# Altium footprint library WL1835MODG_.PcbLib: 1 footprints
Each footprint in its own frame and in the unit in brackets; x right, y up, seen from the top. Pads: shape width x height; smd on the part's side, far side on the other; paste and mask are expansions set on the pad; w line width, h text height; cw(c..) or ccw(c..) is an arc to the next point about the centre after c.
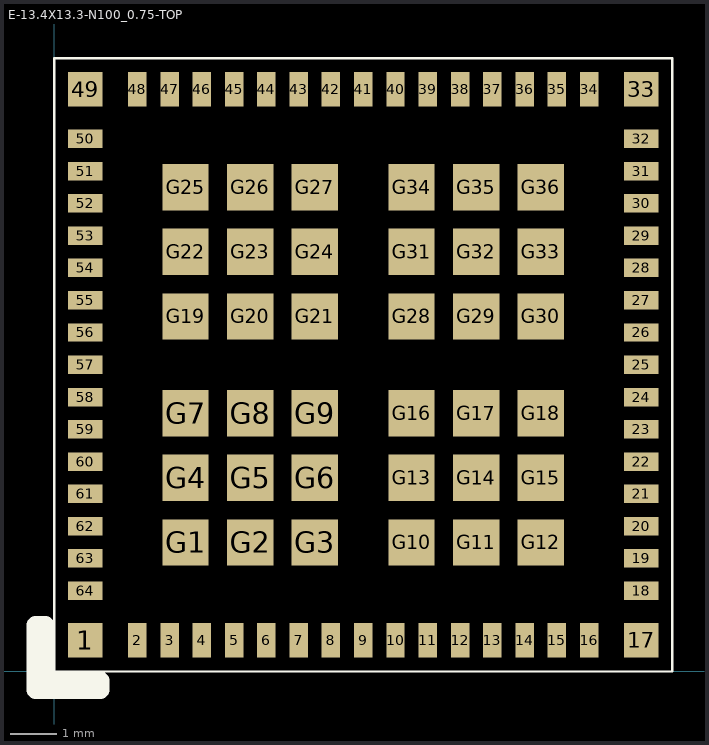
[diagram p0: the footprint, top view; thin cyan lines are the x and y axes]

## E-13.4X13.3-N100_0.75-TOP [mm]
pads (100):
  rect 0.75x0.75 smd mask+0.03: 1(0.675,0.675) 17(12.725,0.675) 33(12.725,12.625) 49(0.675,12.625)
  rect 0.4x0.75 smd mask+0.03: 2(1.8,0.675) 3(2.5,0.675) 4(3.2,0.675) 5(3.9,0.675) 6(4.6,0.675) 7(5.3,0.675) 8(6,0.675) 9(6.7,0.675) 10(7.4,0.675) 11(8.1,0.675) 12(8.8,0.675) 13(9.5,0.675) 14(10.2,0.675) 15(10.9,0.675) 16(11.6,0.675) 34(11.6,12.625) 35(10.9,12.625) 36(10.2,12.625) 37(9.5,12.625) 38(8.8,12.625) 39(8.1,12.625) 40(7.4,12.625) 41(6.7,12.625) 42(6,12.625) 43(5.3,12.625) 44(4.6,12.625) 45(3.9,12.625) 46(3.2,12.625) 47(2.5,12.625) 48(1.8,12.625)
  rect 0.75x0.4 smd mask+0.03: 18(12.725,1.75) 19(12.725,2.45) 20(12.725,3.15) 21(12.725,3.85) 22(12.725,4.55) 23(12.725,5.25) 24(12.725,5.95) 25(12.725,6.65) 26(12.725,7.35) 27(12.725,8.05) 28(12.725,8.75) 29(12.725,9.45) 30(12.725,10.15) 31(12.725,10.85) 32(12.725,11.55) 50(0.675,11.55) 51(0.675,10.85) 52(0.675,10.15) 53(0.675,9.45) 54(0.675,8.75) 55(0.675,8.05) 56(0.675,7.35) 57(0.675,6.65) 58(0.675,5.95) 59(0.675,5.25) 60(0.675,4.55) 61(0.675,3.85) 62(0.675,3.15) 63(0.675,2.45) 64(0.675,1.75)
  rect 1x1 smd mask+0.03: G1(2.85,2.8) G2(4.25,2.8) G3(5.65,2.8) G4(2.85,4.2) G5(4.25,4.2) G6(5.65,4.2) G7(2.85,5.6) G8(4.25,5.6) G9(5.65,5.6) G10(7.75,2.8) G11(9.15,2.8) G12(10.55,2.8) G13(7.75,4.2) G14(9.15,4.2) G15(10.55,4.2) G16(7.75,5.6) G17(9.15,5.6) G18(10.55,5.6) G19(2.85,7.7) G20(4.25,7.7) G21(5.65,7.7) G22(2.85,9.1) G23(4.25,9.1) G24(5.65,9.1) G25(2.85,10.5) G26(4.25,10.5) G27(5.65,10.5) G28(7.75,7.7) G29(9.15,7.7) G30(10.55,7.7) G31(7.75,9.1) G32(9.15,9.1) G33(10.55,9.1) G34(7.75,10.5) G35(9.15,10.5) G36(10.55,10.5)
Top Overlay:
  lines w0.05: 0,0 0,13.3 13.4,13.3 13.4,0 0,0
  lines w0.4: -0.4,-0.4 -0.4,1 -0.2,1 -0.2,-0.2 1,-0.2 1,-0.4 -0.4,-0.4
